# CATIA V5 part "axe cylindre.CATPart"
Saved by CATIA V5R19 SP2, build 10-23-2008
Part number: axe cylindre
Bounding box of the stored display mesh (mm): x -16 to 20, y -25 to 25, z 0 to 55
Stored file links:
  C:\Users\Romain\Documents\IFMA\2A\cours\S3\Projet CFAO-IAO\IAO\Catia\Cylindre\axe cylindre.CATPart
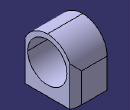
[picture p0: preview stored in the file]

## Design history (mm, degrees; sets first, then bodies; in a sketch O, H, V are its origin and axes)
Body1 (main body)
  Sketch1 on yz-plane, origin (0, 0, 0), H (0, 1, 0), V (0, 0, 1)
    line L1 (0, 0) -> (25, 0)
    point P1 (25, 0)
    line L2 (25, 0) -> (25, 30)
    point P2 (25, 30)
    arc A1 centre (0, 30) radius 25 from (25, 30) to (0, 55) ccw
    point P4 (0, 55)
    point P5 (-25, 0)
    point P6 (0, 0)
    line L3 (0, 0) -> (-25, 0)
    point P7 (-25, 30)
    line L4 (-25, 0) -> (-25, 30)
    point P8 (0, 55)
    arc A2 centre (0, 30) radius 25 from (-25, 30) to (0, 55) cw
    distance P4 O = 55
    radius A1 = 25
    length L1 = 25
    horizontal: L1 H
    vertical: L2 V
    coincidence: P4 V, O P6, P4 P8
    tangency: A1 L2
    symmetry: P1 P5 V, O P6 V, L1 L3 V, P2 P7 V, L2 L4 V, P4 P8 V, A1 A2 V
  Pad1: profile Sketch1, direction (1, 0, 0), length 20
  Sketch2 on xy-plane, origin (0, 0, 0), H (1, 0, 0), V (0, 1, 0)
    point P1 (10, 0)
    reference projected line E1 (20, 0) -> (20, -25) from edge [face of Pad1 from Sketch1.A2 | end face of Pad1]
    arc A1 centre (10, 0) radius 25 from (10.0442, -25) to (10, 25) ccw
    line L1 (10.0442, -25) -> (0, -25.0177)
    point P4 (0, -25.0177)
    line L2 (0, -25) -> (0, 25)
    point P5 (0, -25)
    line L3 (0, 25) -> (10, 25)
    distance P1 E1 = 10
    length L2 = 50
    radius A1 = 25
    coincidence: P1 H, P4 V, P5 V
    tangency: L1 A1, A1 L3
    vertical: L2 V
    horizontal: L3 H
  Pocket1: profile Sketch2, direction (0, 0, 1), through (limit type 3), outer side
  Pad2: profile Sketch1, direction (-1, 0, 0), length 16
  Sketch3 on end face of Pad1, origin (20, 0, 0), H (0, 1, 0), V (0, 0, 1)
    circle A1 centre (0, 30.1956) radius 20
    point P1 (0, 30.1956)
    radius A1 = 20
    coincidence: P1 V
  Pocket2: profile Sketch3, direction (-1, 0, 0), through (limit type 3)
